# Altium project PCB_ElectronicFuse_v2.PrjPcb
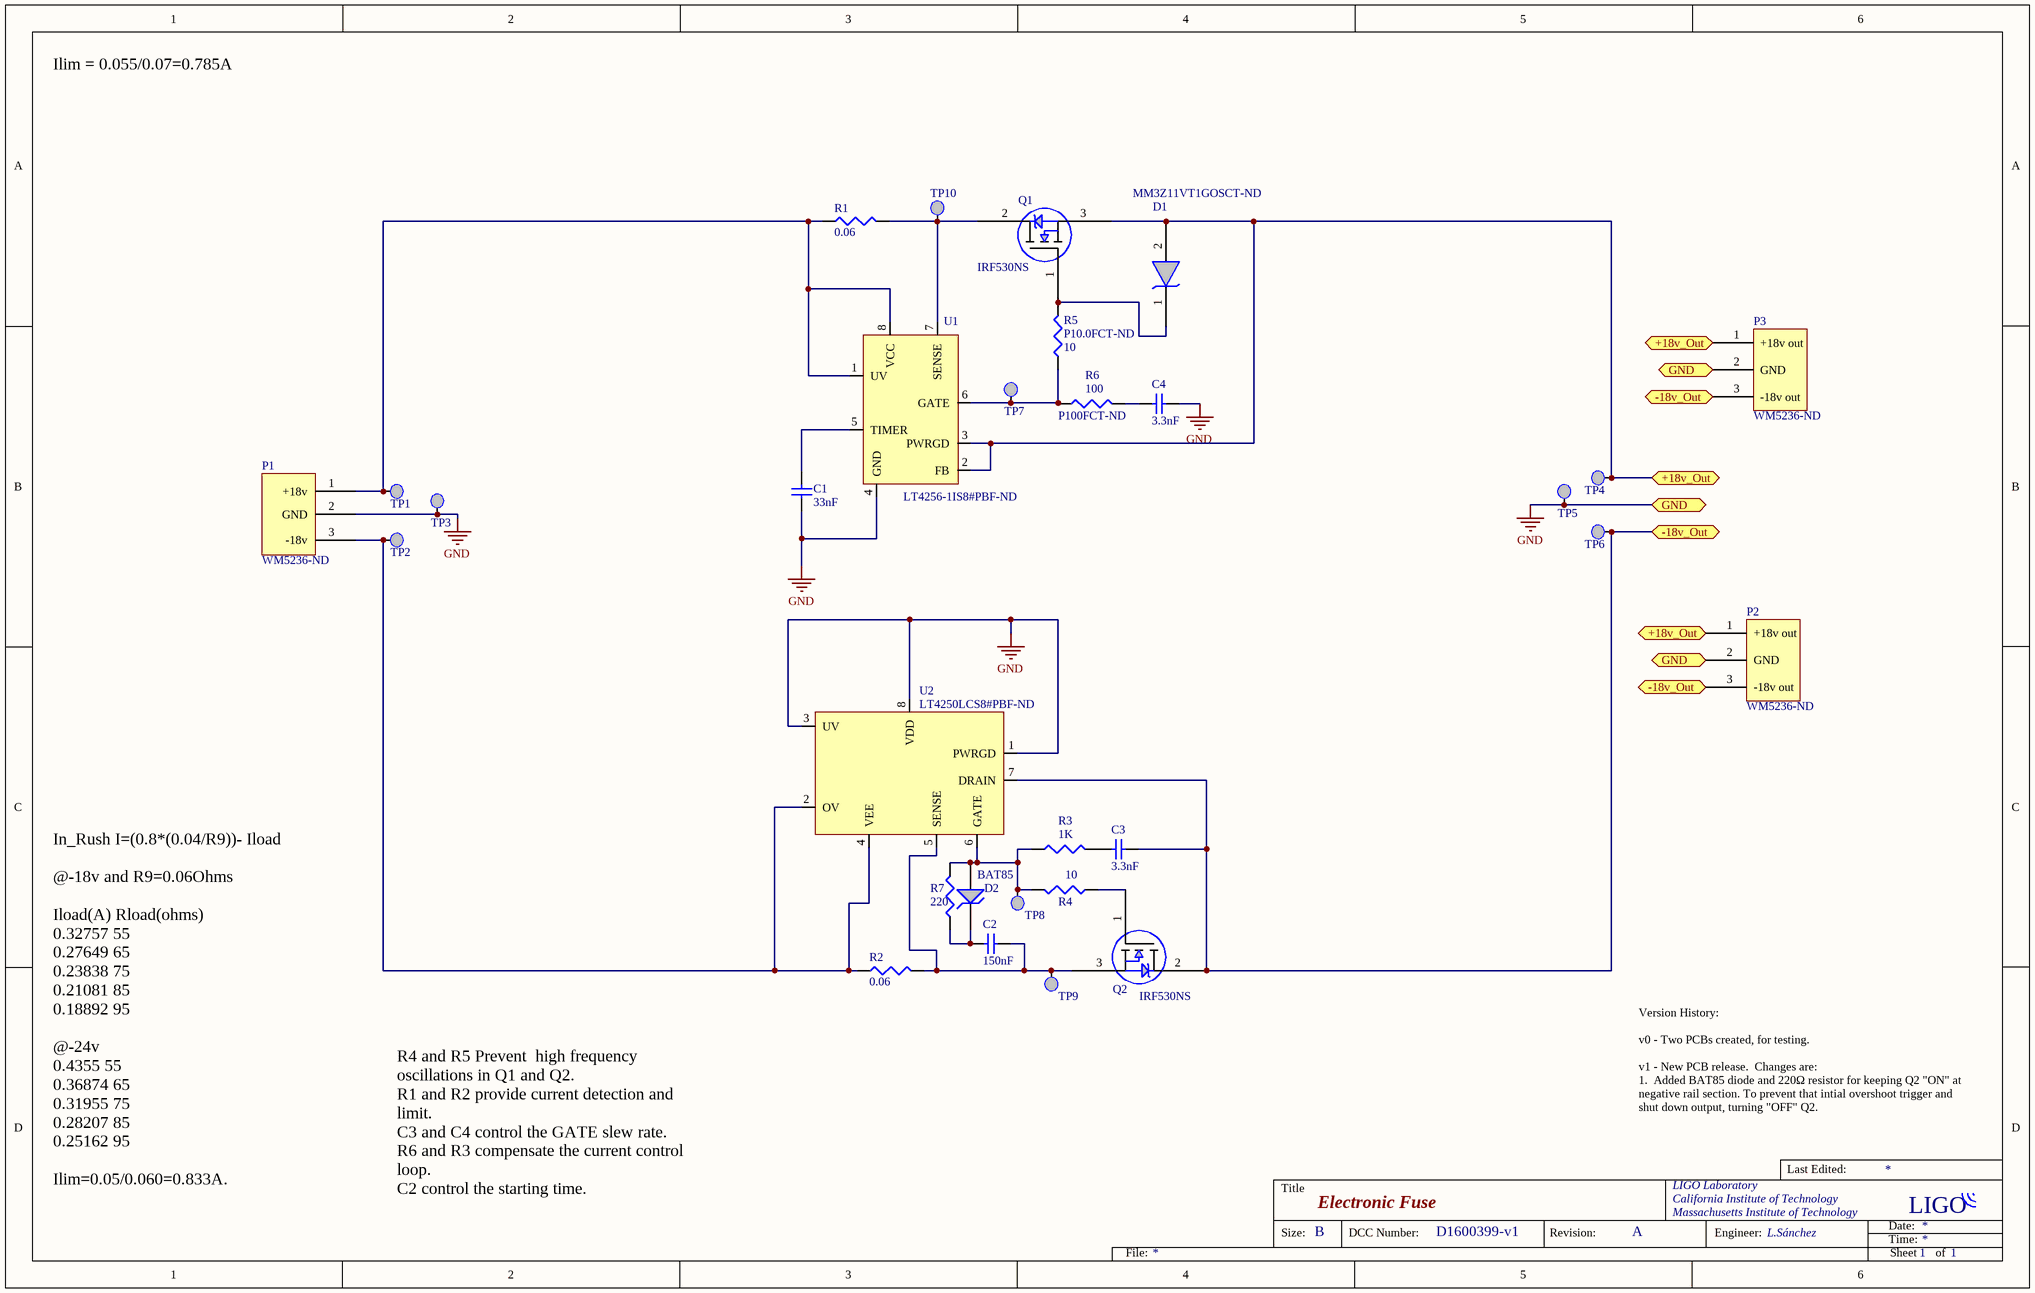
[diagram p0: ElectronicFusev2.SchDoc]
1 sheet, 30 parts. Net scope: flat (ports and power ports of the same name join across sheets).
Board file: ElectronicFuse_Board.PcbDoc

## Sheet ElectronicFusev2.SchDoc: Electronic Fuse
size B; Organization: LIGO Laboratory; Address1: California Institute of Technology; Address2: Massachusetts Institute of Technology; DocumentNumber: D1600399-v1; Revision: A; SheetNumber: 1; SheetTotal: 1; Engineer: L.Sánchez

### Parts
C1  value 33nF  [1206_Cap]  (hidden comment: SMD Capacitor 33nF 50v 1206)
C2  value 150nF  [1206_Cap]  (hidden comment: SMD Capacitor 150nF 50v 1206)
C3  value 3.3nF  [1206_Cap]  (hidden comment: SMD Capacitor 3.3nF 50v X7R 1206)
C4  value 3.3nF  [1206_Cap]  (hidden comment: SMD Capacitor 3.3nF 50v X7R 1206)
D1  MM3Z11VT1GOSCT-ND  [SOD-323]
D2  DIODE SCHOTTKY 40V 200MA SOT323  [SOT323_Single_Diode]  (value not drawn)
P1  Digikey Part Number: WM5236-ND  [MOLEX_156_3P_RA_PS_IN]  (hidden comment: Molex 3p 0.156inch RA)
P2  Digikey Part Number: WM5236-ND  [MOLEX_156_RA_3_PS]  (hidden comment: Molex 3p 0.156inch RA)
P3  Digikey Part Number: WM5236-ND  [Molex_156_RA_3]  (hidden comment: Molex 3p 0.156inch Through Hole RA)
Q1  IRF530NS  [D2PAK]
Q2  IRF530NS  [D2PAK]
R1  value 0.06  [2512]  (hidden comment: SMD Res 2512 0.06ohm 1W 1%)
R2  value 0.06  [2512]  (hidden comment: SMD Res 2512 0.06ohm 1W 1%)
R3  value 1K  [1206]  (hidden comment: SMD Res 1206 1K 0.25W)
R4  value 10  [1206]  (hidden comment: SMD Res 1206 10ohm 0.25W)
R5  value 10  Digikey Part Number: P10.0FCT-ND  [1206]  (hidden comment: SMD Res 1206 10ohm 0.25W)
R6  value 100  Digikey Part Number: P100FCT-ND  [1206]  (hidden comment: SMD Res 1206 100ohm 0.25W)
R7  RES SMD 220 OHM 0.1% 0.4W 1206  [1206]  (value not drawn)
TP1  TESTPT  [smt_tp]  (value not drawn)
TP2  TESTPT  [smt_tp]  (value not drawn)
TP3  TESTPT  [smt_tp]  (value not drawn)
TP4  TESTPT  [smt_tp]  (value not drawn)
TP5  TESTPT  [smt_tp]  (value not drawn)
TP6  TESTPT  [smt_tp]  (value not drawn)
TP7  TESTPT  [smt_tp]  (value not drawn)
TP8  TESTPT  [smt_tp]  (value not drawn)
TP9  TESTPT  [smt_tp]  (value not drawn)
TP10  TESTPT  [smt_tp]  (value not drawn)
U1  Digikey Part Number: LT4256-1IS8#PBF-ND  [SOIC_8P_]  (hidden comment: LT4256-1 Positive High Voltage Hot SwapControllers)
U2  Digikey  Part Number: LT4250LCS8#PBF-ND  [SOIC_8P_]  (hidden comment: LT4250L Neg Voltage Hot SwapController)

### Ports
+18v_Out, -18v_Out, GND

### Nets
GND: C1.1 C4.2 P1.2(GND) P2.2(GND) P3.2(GND) TP3.1 TP5.1 U1.4(GND) U2.1(PWRGD) U2.3(UV) U2.8(VDD) ; port GND
NetC1_2: C1.2 U1.5(TIMER)
NetC2_1: C2.1 Q2.3(S) R2.2 TP9.1 U2.5(SENSE)
NetC2_2: C2.2 D2.3(K) R7.1
NetC3_1: C3.1 R3.2
NetC3_2: C3.2 P2.3(-18v_out) P3.3(-18v_out) Q2.2(D) TP6.1 U2.7(DRAIN) ; port -18v_Out
NetC4_1: C4.1 R6.2
NetD1_1: D1.1(Cathode) Q1.1(G) R5.2
NetD1_2: D1.2(Anode) P2.1(+18v_out) P3.1(+18v_out) Q1.3(S) TP4.1 U1.2(FB) U1.3(PWRGD) ; port +18v_Out
NetD2_1: D2.1(A) R3.1 R4.2 R7.2 TP8.1 U2.6(GATE)
NetP1_1: P1.1(+18v) R1.1 TP1.1 U1.1(UV) U1.8(VCC)
NetP1_3: P1.3(-18v) R2.1 TP2.1 U2.2(OV) U2.4(VEE)
NetQ1_2: Q1.2(D) R1.2 TP10.1 U1.7(SENSE)
NetQ2_1: Q2.1(G) R4.1
NetR5_1: R5.1 R6.1 TP7.1 U1.6(GATE)

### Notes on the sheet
- Ilim = 0.055/0.07=0.785A
- Version History:
  v0 - Two PCBs created, for testing.
  v1 - New PCB release.  Changes are:
  1.  Added BAT85 diode and 220Ω resistor for keeping Q2 "ON" at negative rail section. To prevent that intial overshoot trigger and shut down output, turning "OFF" Q2.
- In_Rush I=(0.8*(0.04/R9))- Iload
  @-18v and R9=0.06Ohms
  Iload(A)	Rload(ohms)
  0.32757	55
  0.27649	65
  0.23838	75
  0.21081	85
  0.18892	95
  @-24v
  0.4355	55
  0.36874	65
  0.31955	75
  0.28207	85
  0.25162	95
  Ilim=0.05/0.060=0.833A.
- R4 and R5 Prevent  high frequency oscillations in Q1 and Q2.
  R1 and R2 provide current detection and limit.
  C3 and C4 control the GATE slew rate.
  R6 and R3 compensate the current control loop.
  C2 control the starting time.

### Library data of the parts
C1 = CAP_1206_33nF: Manufacturers Part Number: 12065C333KAT2A
C2 = CAP_1206_150nF: Manufacturers Part Number: 12065C154KAT2A
C3 C4 = CAP_1206_3.3nF: SMD Capacitor 3.3nF 50v 1206; Manufacturers Part Number: C1206C332K5RACTU
D1 = MM3Z11VT1GOSCT-ND: Zener Diode 11v 300mW SOD-323
D2 = BAT854W_SOT323: Manufacturers Part Number: BAT854W,115; value: BAT85
P1 = Header 3p 156 IN: Manufacturers Part Number: 0026615030
P2 = Header 3p 156 Out PS: Manufacturers Part Number: 0026615030
P3 = Header 3p 156 out: Molex 3p 0.156inch RA; Manufacturers Part Number: 0026615030
Q1 Q2 = IRF530NS: MOSFET N-CH 100V 17A D2PAK; Manufacturers Part Number: IRF530NSTRLPBF
R1 R2 = 2512_0.06: Manufacturers Part Number: WSL2512R0600FEA
R3 = 1206_Res_1K: Manufacturers Part Number: ERJ-8ENF1001V
R4 R5 = 1206_10: Manufacturers Part Number: ERJ-8ENF10R0V
R6 = 1206_100: Manufacturers Part Number: ERJ-8ENF1000V
R7 = 1206_Res_220: Manufacturers Part Number: RTAN1206BKE220R; Checked: Yes; value: 220
TP1-TP10 = TESTPT: PCB Testpoint; 'Manufacturers Part Number: 5016; Checked: Yes; Value: 36-5016CT-ND
U1 = LT4256-1: Hot Swap Controllers 10.8v to 80v; Manufacturers Part Number: LT4256-1CS8#PBF
U2 = LT4250L: Negative Volage Hot Swap Controller; Manufacturers Part Number: LT4250LCS8#PBF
